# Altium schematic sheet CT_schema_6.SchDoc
size 369 x 245 mm
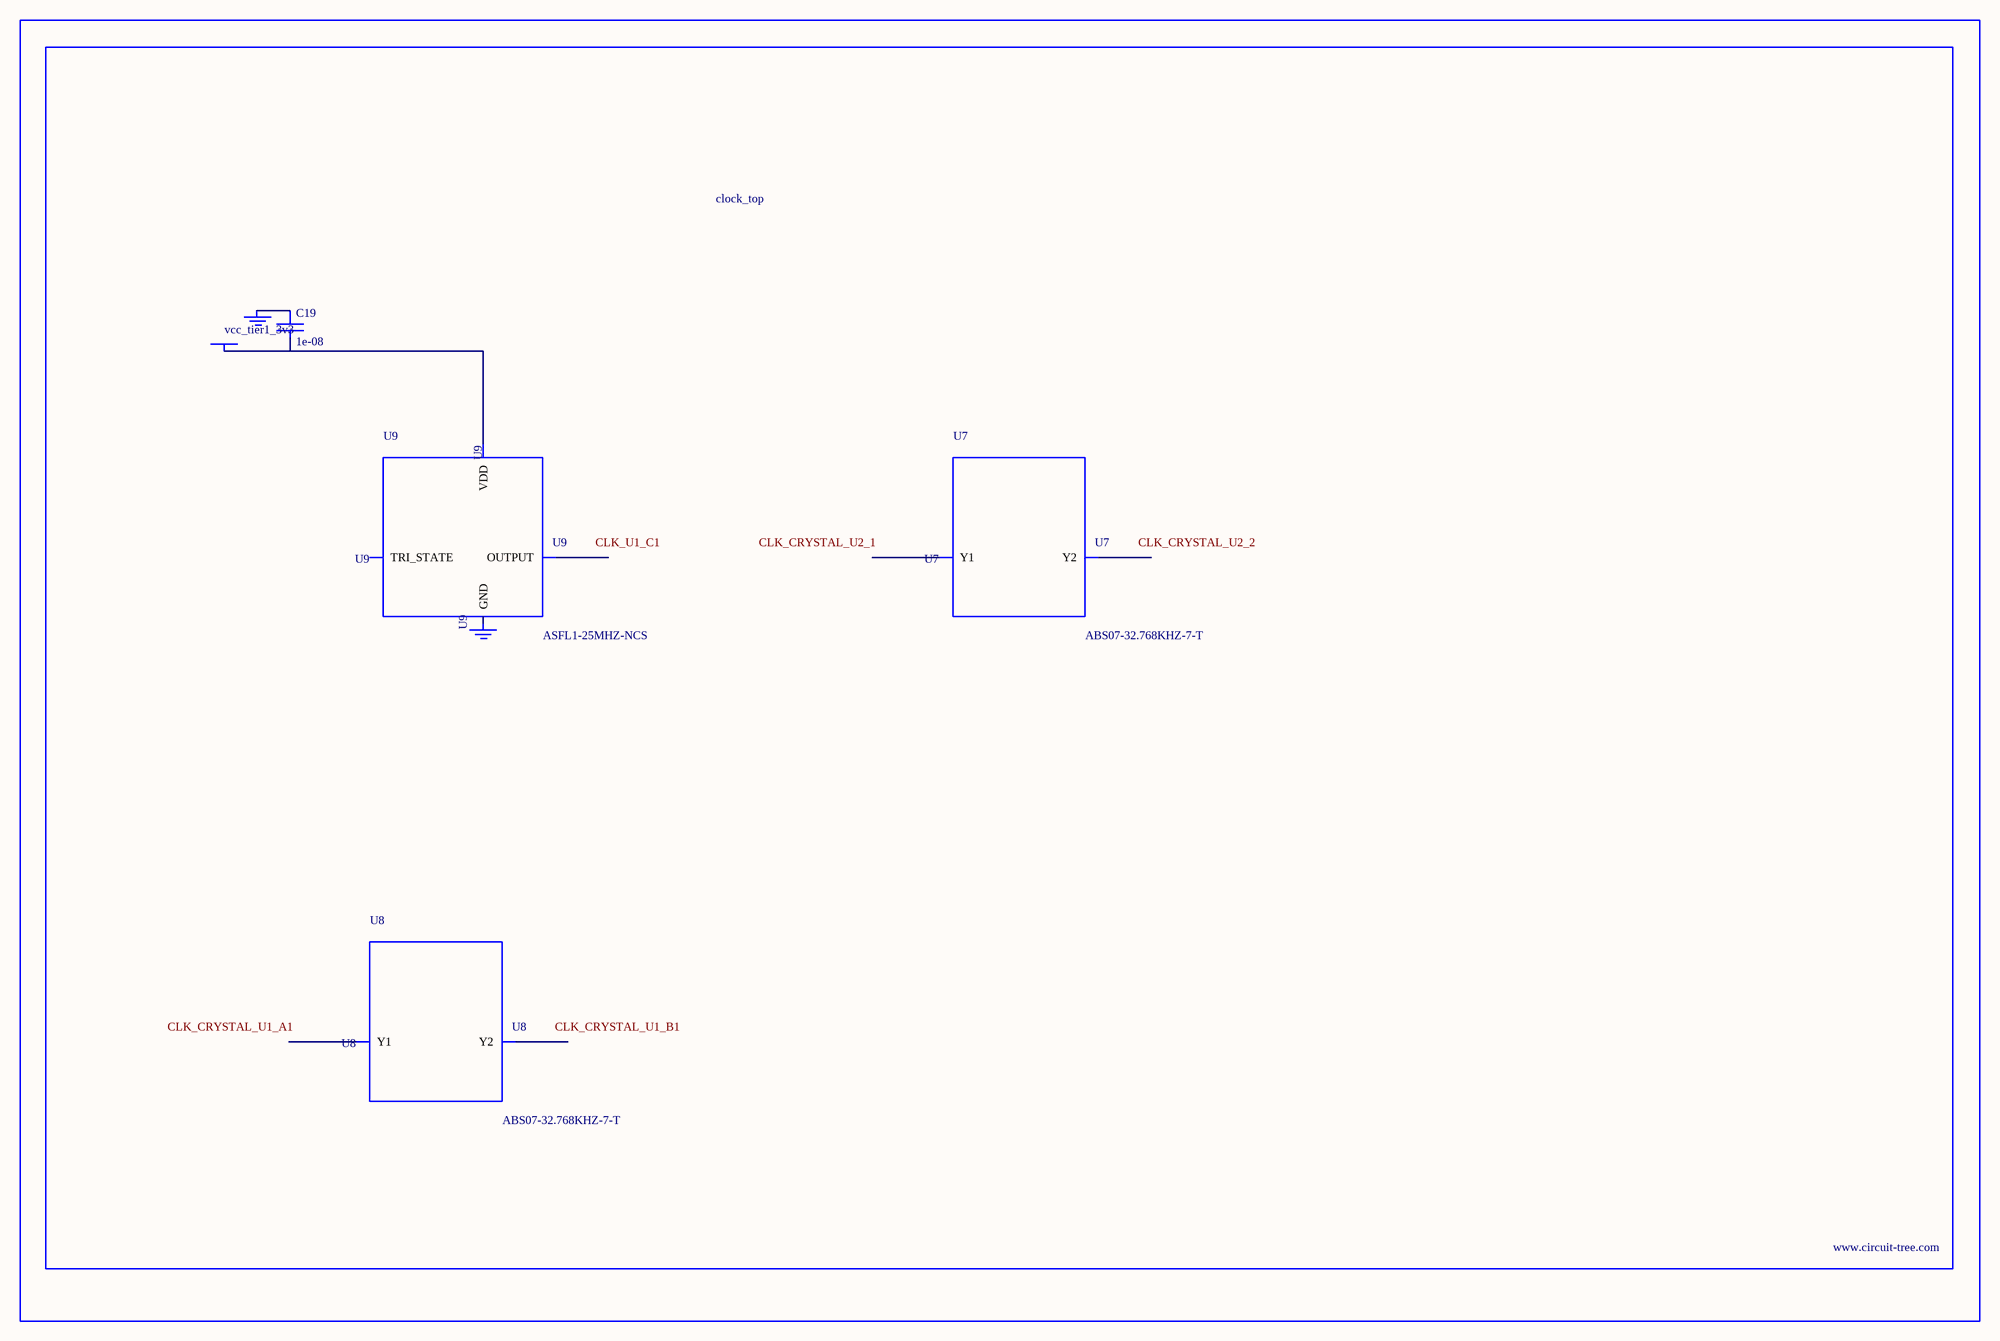
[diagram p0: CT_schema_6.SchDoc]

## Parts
BORDER5  (no value)
C19  1e-08  [C0402]
GND_INSTANCE_5_0  (no value)
GND_INSTANCE_5_1  (no value)
POWER_INSTANCE_5_0  vcc_tier1_3v3
U7  ABS07-32.768KHZ-7-T  [ABS07-32.768KHZ-7-T]
U8  ABS07-32.768KHZ-7-T  [ABS07-32.768KHZ-7-T]
U9  ASFL1-25MHZ-NCS  [ASFL1]

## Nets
NetC19_1: C19.1 GND_INSTANCE_5_0.0(GND)
NetC19_2: C19.2 POWER_INSTANCE_5_0.0(PWR) U9.4(VDD)

Not connected (* = marked no-connect by the designer): GND_INSTANCE_5_1 0(GND); U7 1(Y1) 2(Y2); U8 1(Y1) 2(Y2); U9 1(TRI_STATE) 2(GND) 3(OUTPUT)

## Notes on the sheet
- Labels drawn without touching a wire or pin: CLK_CRYSTAL_U1_A1, CLK_CRYSTAL_U1_B1, CLK_CRYSTAL_U2_1, CLK_CRYSTAL_U2_2, CLK_U1_C1

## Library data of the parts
BORDER5 = BORDER_PAGE5
C19 = C0402C103K3RAC
GND_INSTANCE_5_0 GND_INSTANCE_5_1 = GND
POWER_INSTANCE_5_0 = PWR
